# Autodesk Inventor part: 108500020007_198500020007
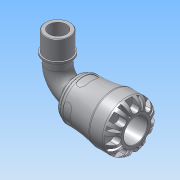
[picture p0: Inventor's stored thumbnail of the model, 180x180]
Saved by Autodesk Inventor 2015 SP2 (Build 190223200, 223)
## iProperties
Created: 2016-12
Part Number: 108500020007_198500020007
Material: PVC-Piping
Description: PLASSON 90° ELBOW WITH THREADED MALE OFFTAKE 20X3/4" SERIES 1
Document SubType Name: Modeling
Designer: KIM
Mass: 664.223 g
Surface Area: 733.008 cm^2
Volume: 474.445 cm^3
Density: 1.4 g/cm^3
Appearance: Smooth - White
Author: KIM
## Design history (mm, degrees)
derived "1085.ipt"
feature "Solid1::1085.ipt"
tag "TaggingFeature1"
body "Solid1"
other parameters: "d1" = 18.9, "d3" = 25, "d4" = 41, "d8" = 34.85, "d13" = 6.4, "d14" = 6.4, "d15" = 0, "d17" = 360 deg, "d19" = 8 deg, "d20" = 0.4, "d21" = 0.4, "d22" = 8 deg, "d24" = 0, "d26" = 360 deg, "d33" = 4.1, "d43" = 31.98, "d51" = 0.41, "d54" = 7, "d55" = 4.4, "d57" = 12.544, "d58" = 0, "d74" = 0, "d78" = 45, "d82" = 0.4, "d115" = 360 deg, "d207" = 90 deg, "d228" = 5.95, "d247" = 0.82, "d248" = 2.7, "d268" = 19.1675, "d269" = 2.7, "d270" = 66, "d276" = 26.441, "d277" = 17, "d278" = 29.0851, "d279" = 42, "d280" = 18.7, "d281" = 3.96615, "d283" = 23.7969, "d286" = 0, "d287" = 0, "d288" = 18.5087, "d290" = 4.09155, "d292" = 30 deg, "E_" = 41, "l_" = 45, "A_" = 66, "A_1" = 42, "l_2" = 17, "R_" = 26.441, "d9" = 8, "d11" = 41, "d12" = 25, "d289" = 18.5087
